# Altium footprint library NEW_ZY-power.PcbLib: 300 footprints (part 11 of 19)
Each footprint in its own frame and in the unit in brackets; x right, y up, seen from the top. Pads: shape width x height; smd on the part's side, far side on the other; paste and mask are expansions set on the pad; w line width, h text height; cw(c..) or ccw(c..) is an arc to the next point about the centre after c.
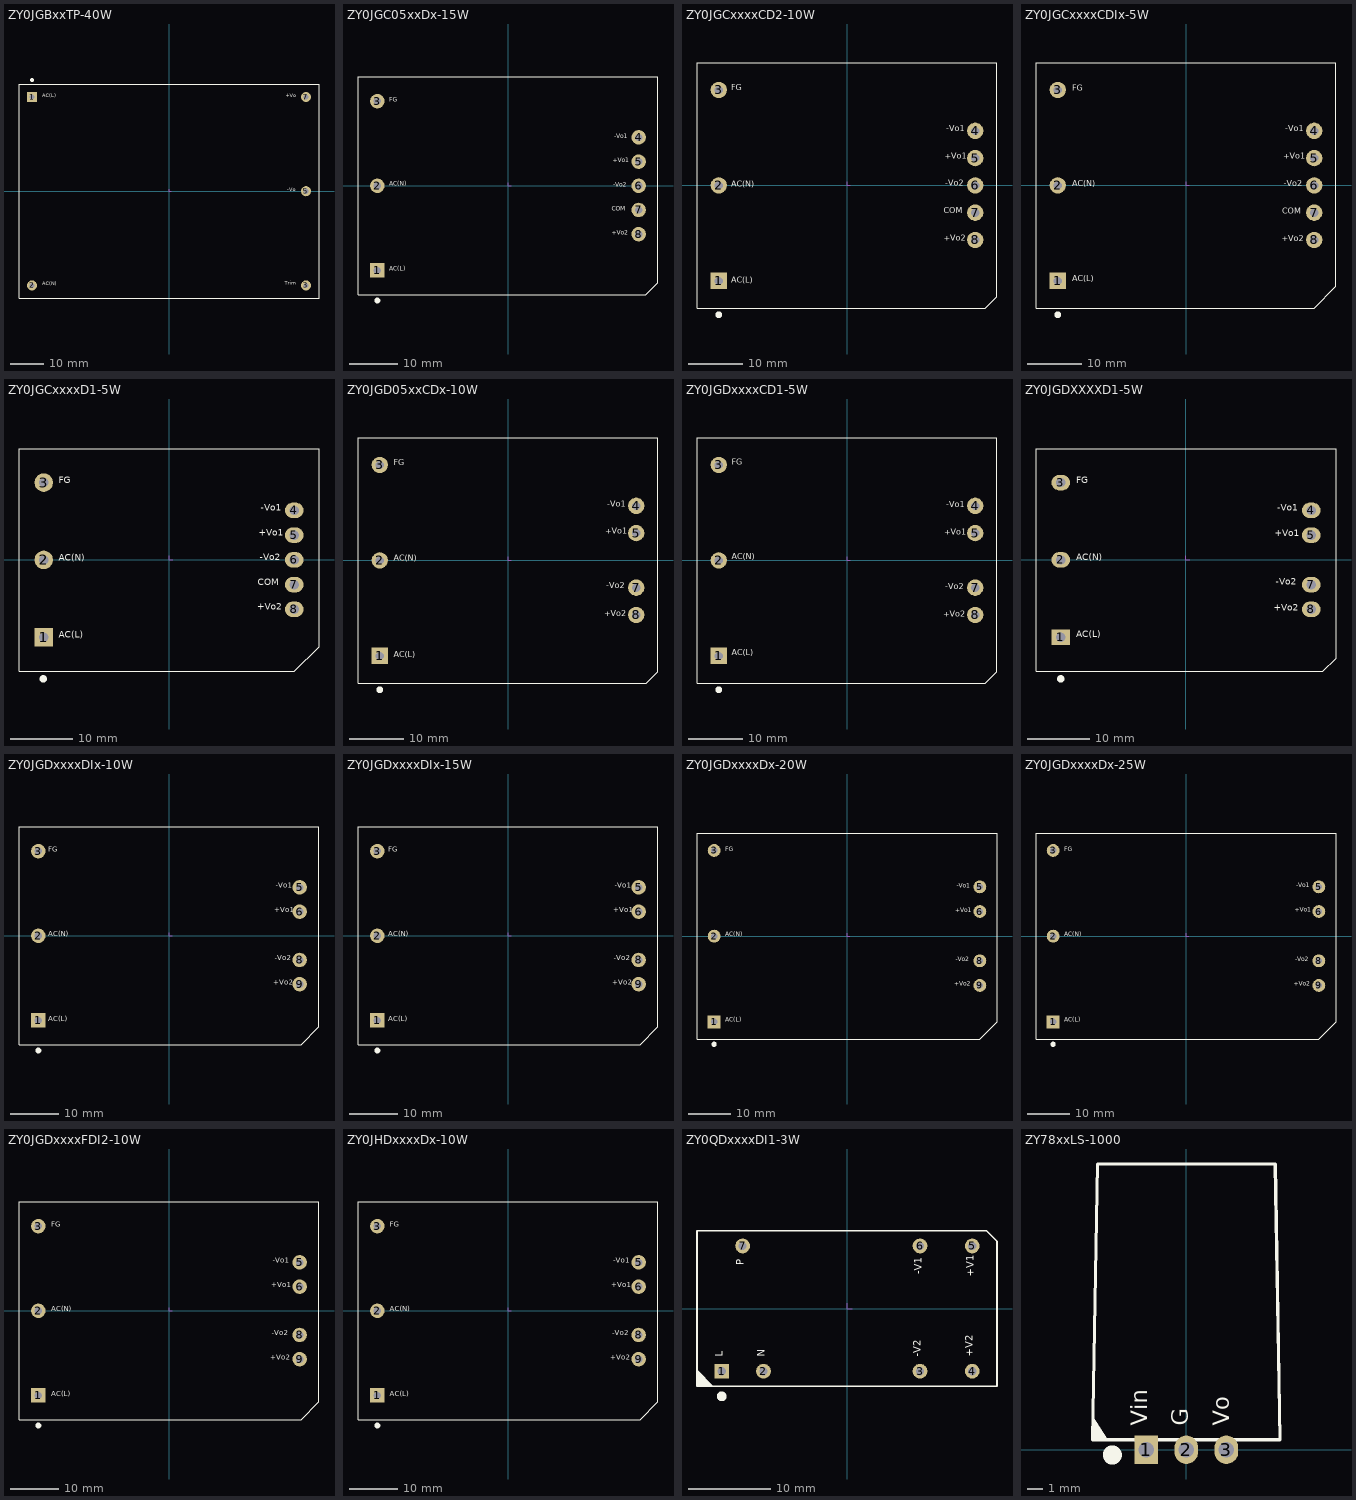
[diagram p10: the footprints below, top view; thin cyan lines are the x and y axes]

## ZY0JGBxxTP-40W [mm]
height 25
pads (5):
  rect 3x3 hole 1.5: 1(-40.64,27.94)
  round 3 hole 1.5: 2(-40.64,-27.94) 3(40.64,-27.94) 5(40.64,0) 7(40.64,27.94)
Top Overlay:
  circle w1: c-40.64,32.975 r0.1
  lines w0.2: -44.5,-31.75 -44.5,31.75 44.5,31.75 44.5,-31.75 -44.5,-31.75
  text "Trim" at 34.332,-28.245 h1.78
  text "AC(L)" at -37.592,27.508 h1.78
  text "+Vo" at 34.644,27.407 h1.78
  text "AC(N)" at -37.592,-28.372 h1.78
  text "-Vo" at 35.009,-0.483 h1.78
Mechanical 15:
  lines w0.127: 0,0.635 0,0 0.635,0

## ZY0JGC05xxDx-15W [mm]
height 22.5
pads (8):
  rect 3x3 hole 1.5: 1(-27,-17.5)
  round 3 hole 1.5: 2(-27,0) 3(-27,17.5) 4(27,10) 5(27,5) 6(27,0) 7(27,-5) 8(27,-10)
Top Overlay:
  circle w1: c-27,-23.725 r0.1
  lines w0.2: -31,-22.5 28.503,-22.5 31,-20.003 31,22.5 -31,22.5 -31,-22.5
  text "-Vo1" at 21.912,9.5 h1.52
  text "+Vo2" at 21.422,-10.439 h1.52
  text "FG" at -24.592,17.043 h1.52
  text "AC(N)" at -24.592,-0.267 h1.52
  text "AC(L)" at -24.592,-17.882 h1.52
  text "+Vo1" at 21.6,4.516 h1.52
  text "-Vo2" at 21.734,-0.469 h1.52
  text "COM" at 21.49,-5.454 h1.52
Mechanical 15:
  lines w0.127: 0,0.635 0,0 0.635,0

## ZY0JGCxxxxCD2-10W [mm]
height 20.5
pads (8):
  rect 3x3 hole 1.5: 1(-23.5,-17.5)
  round 3 hole 1.5: 2(-23.5,0) 3(-23.5,17.5) 4(23.5,10) 5(23.5,5) 6(23.5,0) 7(23.5,-5) 8(23.5,-10)
Top Overlay:
  circle w1: c-23.5,-23.725 r0.1
  lines w0.2: -27.5,-22.5 25.379,-22.5 27.5,-20.379 27.5,22.5 -27.5,22.5 -27.5,-22.5
  text "+Vo2" at 17.701,-10.49 h1.78
  text "-Vo2" at 18.013,-0.47 h1.78
  text "-Vo1" at 18.192,9.55 h1.78
  text "COM" at 17.77,-5.48 h1.78
  text "+Vo1" at 17.88,4.54 h1.78
  text "FG" at -21.214,17.043 h1.78
  text "AC(N)" at -21.214,-0.572 h1.78
  text "AC(L)" at -21.214,-18.186 h1.78
Mechanical 15:
  lines w0.127: 0,0.635 0,0 0.635,0

## ZY0JGCxxxxCDIx-5W [mm]
height 20.5
pads (8):
  rect 3x3 hole 1.5: 1(-23.5,-17.5)
  round 3 hole 1.5: 2(-23.5,0) 3(-23.5,17.5) 4(23.5,10) 5(23.5,5) 6(23.5,0) 7(23.5,-5) 8(23.5,-10)
Top Overlay:
  circle w1: c-23.5,-23.725 r0.1
  lines w0.2: -27.5,-22.5 23.5,-22.5 27.5,-18.5 27.5,22.5 -27.5,22.5 -27.5,-22.5
  text "COM" at 17.668,-5.544 h1.78
  text "FG" at -20.828,17.018 h1.78
  text "AC(N)" at -20.828,-0.508 h1.78
  text "-Vo1" at 18.161,9.525 h1.78
  text "+Vo1" at 17.797,4.502 h1.78
  text "AC(L)" at -20.828,-17.983 h1.78
  text "-Vo2" at 17.953,-0.521 h1.78
  text "+Vo2" at 17.588,-10.566 h1.78
Mechanical 15:
  lines w0.127: 0,0.635 0,0 0.635,0

## ZY0JGCxxxxD1-5W [mm]
height 20.5
pads (8):
  rect 3x3 hole 1.5: 1(-20.25,-12.5)
  round 3 hole 1.5: 2(-20.25,0) 3(-20.25,12.5)
  oval 3x2.5 hole 1.5: 4(20.25,8) 5(20.25,4) 6(20.25,0) 7(20.25,-4) 8(20.25,-8)
Top Overlay:
  circle w1: c-20.325,-19.225 r0.1
  lines w0.2: -24.25,-18 -24.25,18 24.25,18 24.25,-14 20.25,-18 -24.25,-18
  text "AC(L)" at -17.831,-12.954 h1.78
  text "+Vo1" at 14.495,3.518 h1.78
  text "-Vo1" at 14.859,7.518 h1.78
  text "AC(N)" at -17.831,-0.533 h1.78
  text "FG" at -17.831,12.014 h1.78
  text "COM" at 14.366,-4.483 h1.78
  text "-Vo2" at 14.651,-0.483 h1.78
  text "+Vo2" at 14.286,-8.484 h1.78
Mechanical 15:
  lines w0.127: 0,0.635 0,0 0.635,0

## ZY0JGD05xxCDx-10W [mm]
pads (7):
  rect 3x3 hole 1.5: 1(-23.5,-17.5)
  round 3 hole 1.5: 2(-23.5,0) 3(-23.5,17.5) 4(23.5,10) 5(23.5,5) 7(23.5,-5) 8(23.5,-10)
Top Overlay:
  circle w1: c-23.5,-23.725 r0.1
  lines w0.2: -27.5,-22.5 -27.5,22.5 27.5,22.5 27.5,-20.379 25.379,-22.5 -27.5,-22.5
  text "-Vo2" at 18.022,-5.5 h1.78
  text "+Vo1" at 17.866,4.5 h1.78
  text "AC(L)" at -20.96,-18.161 h1.78
  text "AC(N)" at -20.96,-0.457 h1.78
  text "FG" at -20.96,17.069 h1.78
  text "+Vo2" at 17.658,-10.566 h1.78
  text "-Vo1" at 18.23,9.5 h1.78
Mechanical 15:
  lines w0.127: 0,0.635 0,0 0.635,0

## ZY0JGDxxxxCD1-5W [mm]
pads (7):
  rect 3x3 hole 1.5: 1(-23.5,-17.5)
  round 3 hole 1.5: 2(-23.5,0) 3(-23.5,17.5) 4(23.5,10) 5(23.5,5) 7(23.5,-5) 8(23.5,-10)
Top Overlay:
  circle w1: c-23.5,-23.725 r0.1
  lines w0.2: -27.5,-22.5 -27.5,22.5 27.5,22.5 27.5,-20.379 25.379,-22.5 -27.5,-22.5
  text "-Vo2" at 18.022,-5.627 h1.78
  text "+Vo1" at 17.866,4.373 h1.78
  text "AC(L)" at -21.087,-17.729 h1.78
  text "AC(N)" at -21.087,-0.203 h1.78
  text "FG" at -21.087,17.196 h1.78
  text "+Vo2" at 17.658,-10.693 h1.78
  text "-Vo1" at 18.23,9.373 h1.78
Mechanical 15:
  lines w0.127: 0,0.635 0,0 0.635,0

## ZY0JGDXXXXD1-5W [mm]
pads (7):
  rect 3x2.5 hole 1.5: 1(-20.25,-12.5)
  oval 3x2.5 hole 1.5: 2(-20.25,0) 3(-20.25,12.5) 4(20.25,8) 5(20.25,4) 7(20.25,-4) 8(20.25,-8)
Top Overlay:
  circle w1: c-20.25,-19.225 r0.1
  lines w0.2: -24.25,-18 22.129,-18 24.25,-15.879 24.25,18 -24.25,18 -24.25,-18
  text "-Vo1" at 14.726,7.544 h1.78
  text "+Vo2" at 14.154,-8.585 h1.78
  text "FG" at -17.71,11.963 h1.78
  text "AC(N)" at -17.71,-0.432 h1.78
  text "AC(L)" at -17.71,-12.878 h1.78
  text "+Vo1" at 14.362,3.429 h1.78
  text "-Vo2" at 14.518,-4.445 h1.78
Mechanical 15:
  lines w0.127: 0,0.635 0,0 0.635,0

## ZY0JGDxxxxDIx-10W [mm]
height 22.5
pads (7):
  rect 3x3 hole 1.5: 1(-27,-17.5)
  round 3 hole 1.5: 2(-27,0) 3(-27,17.5) 5(27,10) 6(27,5) 8(27,-5) 9(27,-10)
Top Overlay:
  circle w1: c-27,-23.725 r0.1
  lines w0.2: -31,-22.5 -31,22.5 31,22.5 31,-18.825 27.325,-22.5 -31,-22.5
  text "FG" at -24.968,16.942 h1.78
  text "AC(N)" at -24.968,-0.457 h1.78
  text "AC(L)" at -24.968,-18.034 h1.78
  text "-Vo2" at 21.903,-5.5 h1.78
  text "+Vo1" at 21.747,4.5 h1.78
  text "+Vo2" at 21.539,-10.566 h1.78
  text "-Vo1" at 22.111,9.5 h1.78
Mechanical 15:
  lines w0.127: 0,0.635 0,0 0.635,0

## ZY0JGDxxxxDIx-15W [mm]
pads (7):
  rect 3x3 hole 1.5: 1(-27,-17.5)
  round 3 hole 1.5: 2(-27,0) 3(-27,17.5) 5(27,10) 6(27,5) 8(27,-5) 9(27,-10)
Top Overlay:
  circle w1: c-27,-23.725 r0.1
  lines w0.2: -31,-22.5 -31,22.5 31,22.5 31,-18.825 27.325,-22.5 -31,-22.5
  text "FG" at -24.714,16.942 h1.78
  text "AC(N)" at -24.714,-0.457 h1.78
  text "AC(L)" at -24.714,-18.034 h1.78
  text "-Vo2" at 21.851,-5.5 h1.78
  text "+Vo1" at 21.717,4.5 h1.78
  text "+Vo2" at 21.539,-10.566 h1.78
  text "-Vo1" at 22.029,9.5 h1.78
Mechanical 15:
  lines w0.127: 0,0.635 0,0 0.635,0

## ZY0JGDxxxxDx-20W [mm]
height 23.5
pads (7):
  rect 3x3 hole 1.5: 1(-31,-20)
  round 3 hole 1.5: 2(-31,0) 3(-31,20) 5(31,11.5) 6(31,5.75) 8(31,-5.75) 9(31,-11.5)
Top Overlay:
  circle w1: c-31,-25.228 r0.1
  lines w0.2: -35,-24.003 -35,24 35,24 35,-19.991 30.988,-24.003 -35,-24.003
  text "+Vo1" at 25.239,5.207 h1.78
  text "-Vo1" at 25.603,10.922 h1.78
  text "-Vo2" at 25.395,-6.223 h1.78
  text "+Vo2" at 25.031,-11.938 h1.78
  text "AC(L)" at -28.46,-20.356 h1.78
  text "AC(N)" at -28.46,-0.356 h1.78
  text "FG" at -28.46,19.431 h1.78
Mechanical 15:
  lines w0.127: 0,0.635 0,0 0.635,0

## ZY0JGDxxxxDx-25W [mm]
pads (7):
  rect 3x3 hole 1.5: 1(-31,-20)
  round 3 hole 1.5: 2(-31,0) 3(-31,20) 5(31,11.5) 6(31,5.75) 8(31,-5.75) 9(31,-11.5)
Top Overlay:
  circle w1: c-31,-25.228 r0.1
  lines w0.2: -35,-24.003 30.988,-24.003 35,-19.991 35,24 -35,24 -35,-24.003
  text "FG" at -28.46,19.431 h1.78
  text "AC(N)" at -28.46,-0.356 h1.78
  text "AC(L)" at -28.46,-20.356 h1.78
  text "+Vo2" at 25.158,-11.938 h1.78
  text "-Vo2" at 25.522,-6.223 h1.78
  text "-Vo1" at 25.73,11.049 h1.78
  text "+Vo1" at 25.366,5.334 h1.78
Mechanical 15:
  lines w0.127: 0,0.635 0,0 0.635,0

## ZY0JGDxxxxFDI2-10W [mm]
pads (7):
  rect 3x3 hole 1.5: 1(-27,-17.5)
  round 3 hole 1.5: 2(-27,0) 3(-27,17.5) 5(27,10) 6(27,5) 8(27,-5) 9(27,-10)
Top Overlay:
  circle w1: c-27,-23.725 r0.1
  lines w0.2: -31,-22.5 -31,22.5 31,22.5 31,-18.825 27.325,-22.5 -31,-22.5
  text "FG" at -24.333,16.942 h1.78
  text "AC(N)" at -24.333,-0.457 h1.78
  text "AC(L)" at -24.333,-18.034 h1.78
  text "-Vo2" at 21.268,-5.5 h1.78
  text "+Vo1" at 21.112,4.5 h1.78
  text "+Vo2" at 20.904,-10.566 h1.78
  text "-Vo1" at 21.476,9.5 h1.78
Mechanical 15:
  lines w0.127: 0,0.635 0,0 0.635,0

## ZY0JHDxxxxDx-10W [mm]
pads (7):
  rect 3x3 hole 1.5: 1(-27,-17.5)
  round 3 hole 1.5: 2(-27,0) 3(-27,17.5) 5(27,10) 6(27,5) 8(27,-5) 9(27,-10)
Top Overlay:
  circle w1: c-27,-23.725 r0.1
  lines w0.2: -31,-22.5 27.325,-22.5 31,-18.825 31,22.5 -31,22.5 -31,-22.5
  text "-Vo1" at 21.73,9.5 h1.78
  text "+Vo2" at 21.158,-10.566 h1.78
  text "+Vo1" at 21.366,4.5 h1.78
  text "-Vo2" at 21.522,-5.5 h1.78
  text "AC(L)" at -24.46,-18.034 h1.78
  text "AC(N)" at -24.46,-0.457 h1.78
  text "FG" at -24.46,16.942 h1.78
Mechanical 15:
  lines w0.127: 0,0.635 0,0 0.635,0

## ZY0QDxxxxDI1-3W [mm]
height 17.2
pads (7):
  rect 1.8x1.8 hole 1: 1(-15.24,-7.62)
  round 1.8 hole 1: 2(-10.16,-7.62) 3(8.89,-7.62) 4(15.24,-7.62) 5(15.24,7.62) 6(8.89,7.62) 7(-12.7,7.62)
Top Overlay:
  circle w1: c-15.245,-10.675 r0.1
  region: -18.25,-9.45 -16.275,-9.45 -18.25,-7.475
  lines w0.2: -18.25,-9.45 18.25,-9.45 18.25,8.18 16.98,9.45 -18.25,9.45 -18.25,-9.45
  text "-V1" at 9.398,4.198 h1.52
  text "+V1" at 15.697,3.886 h1.52
  text "+V2" at 15.596,-5.842 h1.52
  text "-V2" at 9.296,-5.842 h1.52
  text "N" at -9.703,-5.842 h1.52
  text "L" at -14.808,-5.842 h1.52
  text "P" at -12.268,5.281 h1.52
Mechanical 15:
  lines w0.127: 0,0.635 0,0 0.635,0

## ZY78xxLS-1000 [mm]
height 10
pads (3):
  rect 1.5x1.8 hole 1: 1(-2.54,0)
  oval 1.5x1.8 hole 1: 2(0,0) 3(2.54,0)
Top Overlay:
  circle w1: c-4.699,-0.327 r0.1
  region: -5.991,2.229 -5.991,0.644 -4.997,0.644
  lines w0.2: -5.95,0.644 -5.645,18.144 5.645,18.144 5.95,0.644 -5.95,0.644
  text "Vin" at -2.134,1.524 h1.78
  text "G" at 0.483,1.524 h1.78
  text "Vo" at 3.073,1.524 h1.78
